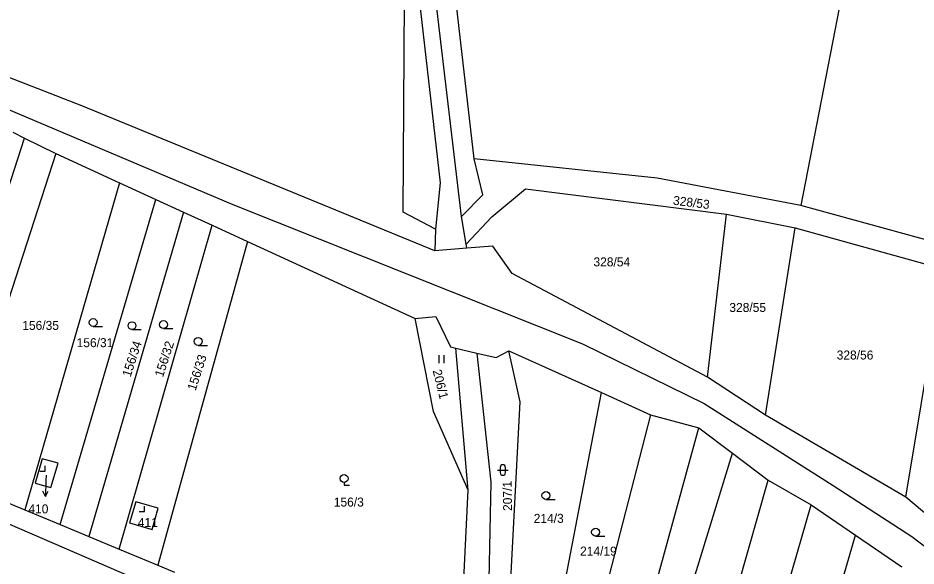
# Model space of a CAD drawing. Extents: x -783948 to -781889, y -1005870 to -1004430.
# Drawn here: x -782682.3 to -782512.1, y -1005229.8 to -1005126 of the extents above; entities that cross this region are included whole.
import ezdxf

# ---------------------------------------------------------------- set-up
doc = ezdxf.new("R2010")
doc.units = 0
for name, color, linetype in [('Vrstva 1', 7, 'Continuous'), ('Vrstva 2', 7, 'Continuous'), ('Vrstva 3', 7, 'Continuous'), ('Vrstva 6', 7, 'Continuous'), ('Vrstva 7', 7, 'Continuous')]:
    doc.layers.add(name, color=color, linetype=linetype)

msp = doc.modelspace()

# ---------------------------------------------------------------- linework, layer by layer
at = {"layer": 'Vrstva 1'}
for p, q in [((-782683.3, -1005147.64), (-782681.06, -1005148.77)), ((-782700.91, -1005209.8), (-782681.06, -1005148.77)), ((-782681.06, -1005148.77), (-782675.11, -1005151.66)), ((-782675.11, -1005151.66), (-782694.84, -1005212.38)), ((-782675.11, -1005151.66), (-782663.04, -1005157.2)), ((-782663.04, -1005157.2), (-782681.01, -1005219.18)), ((-782663.04, -1005157.2), (-782656.17, -1005160.35)), ((-782674.31, -1005221.97), (-782656.17, -1005160.35)), ((-782656.17, -1005160.35), (-782650.91, -1005162.76)), ((-782506.17, -1005169.11), (-782533.94, -1005161.48)), ((-782650.91, -1005162.76), (-782668.89, -1005224.22)), ((-782650.91, -1005162.76), (-782645.48, -1005165.25)), ((-782551.65, -1005194.04), (-782548.07, -1005163.13)), ((-782548.07, -1005163.13), (-782535.05, -1005165.75)), ((-782597.38, -1005168.84), (-782598.25, -1005163.56)), ((-782663.16, -1005226.6), (-782645.48, -1005165.25)), ((-782645.48, -1005165.25), (-782638.79, -1005168.32)), ((-782603.17, -1005166.01), (-782603.34, -1005170.09)), ((-782540.66, -1005201.24), (-782535.05, -1005165.75)), ((-782535.05, -1005165.75), (-782506.92, -1005173.54)), ((-782638.79, -1005168.32), (-782655.82, -1005229.65)), ((-782638.79, -1005168.32), (-782607.01, -1005182.91)), ((-782597.26, -1005169.59), (-782603.34, -1005170.09)), ((-782597.26, -1005169.59), (-782597.38, -1005168.84)), ((-782514.05, -1005216.76), (-782506.92, -1005173.54)), ((-782599.33, -1005188.51), (-782595.36, -1005189.48)), ((-782596.97, -1005215.45), (-782599.33, -1005188.51)), ((-782589.32, -1005189.04), (-782571.74, -1005196.93)), ((-782540.66, -1005201.24), (-782551.65, -1005194.04)), ((-782586.82, -1005275.72), (-782571.74, -1005196.93)), ((-782571.74, -1005196.93), (-782562.45, -1005201.15)), ((-782562.45, -1005201.15), (-782581.31, -1005274.34)), ((-782562.45, -1005201.15), (-782553.29, -1005203.6)), ((-782514.05, -1005216.76), (-782540.66, -1005201.24)), ((-782573.67, -1005278.05), (-782553.29, -1005203.6)), ((-782553.29, -1005203.6), (-782546.93, -1005208.45)), ((-782569, -1005280.32), (-782546.93, -1005208.45)), ((-782546.93, -1005208.45), (-782540.15, -1005213.57)), ((-782695.19, -1005213.28), (-782681.01, -1005219.18)), ((-782560.39, -1005284.52), (-782540.15, -1005213.57)), ((-782540.15, -1005213.57), (-782531.97, -1005218.22)), ((-782652.68, -1005235.38), (-782700.06, -1005214.94)), ((-782681.01, -1005219.18), (-782674.31, -1005221.97)), ((-782551.57, -1005285.44), (-782531.97, -1005218.22)), ((-782531.97, -1005218.22), (-782523.58, -1005223.98)), ((-782674.31, -1005221.97), (-782668.89, -1005224.22)), ((-782668.89, -1005224.22), (-782663.16, -1005226.6)), ((-782541.74, -1005286.41), (-782523.58, -1005223.98)), ((-782523.58, -1005223.98), (-782514.79, -1005229.97)), ((-782663.16, -1005226.6), (-782655.82, -1005229.65)), ((-782655.82, -1005229.65), (-782652.65, -1005230.97))]:
    msp.add_line(p, q, dxfattribs=at)
for points in [[(-782603.17, -1005166.01), (-782609.32, -1005162.79), (-782608.8, -1005082.15), (-782604.16, -1005035.19), (-782599.71, -1005013.15), (-782586.95, -1004973.45)], [(-782586.95, -1004973.45), (-782597.75, -1005020.65), (-782600.85, -1005037.62), (-782602.65, -1005059.62), (-782606.52, -1005120.13), (-782602.3, -1005157.2), (-782603.17, -1005166.01)], [(-782598.25, -1005163.56), (-782603.01, -1005123.54), (-782599.4, -1005065.13), (-782594.84, -1005033.29), (-782586.07, -1004994.91)], [(-782595.88, -1005152.67), (-782599.4, -1005121.85), (-782597.87, -1005069.24), (-782592.64, -1005033.25), (-782584.34, -1004995.55)], [(-782483.01, -1005052.11), (-782511.95, -1005043.46), (-782520.61, -1005092.84), (-782533.94, -1005161.48)], [(-782603.34, -1005170.09), (-782670.21, -1005142.63), (-782705.63, -1005128.88), (-782803.2, -1005086.94), (-782810.41, -1005084.95), (-782850.5, -1005065.89)], [(-782598.25, -1005163.56), (-782594.21, -1005159.46), (-782595.88, -1005152.67)], [(-782533.94, -1005161.48), (-782561.15, -1005156.31), (-782595.88, -1005152.67)], [(-782597.38, -1005168.84), (-782592.52, -1005163.67), (-782586.11, -1005158.34), (-782548.07, -1005163.13)], [(-782551.65, -1005194.04), (-782588.65, -1005174.4), (-782592.33, -1005169.18), (-782597.26, -1005169.59)], [(-782607.01, -1005182.91), (-782603.11, -1005182.52), (-782600.34, -1005188.27), (-782599.33, -1005188.51)], [(-782596.97, -1005215.45), (-782603.56, -1005200.53), (-782607.01, -1005182.91)], [(-782595.36, -1005189.48), (-782591.71, -1005190.27), (-782589.32, -1005189.04)], [(-782595.36, -1005189.48), (-782592.73, -1005213.92), (-782593.1, -1005232.35), (-782594, -1005268.18)], [(-782590.78, -1005268.46), (-782587.12, -1005198.7), (-782589.32, -1005189.04)], [(-782674.71, -1005210.35), (-782677.69, -1005209.49), (-782679.03, -1005214.11), (-782676.06, -1005214.96), (-782674.71, -1005210.35)], [(-782601.33, -1005274.67), (-782599.52, -1005267.38), (-782596.97, -1005215.45)], [(-782660, -1005217.63), (-782661.16, -1005221.64), (-782656.9, -1005222.87), (-782655.74, -1005218.86), (-782660, -1005217.63)], [(-782402.29, -1005331.02), (-782436.69, -1005287.11), (-782455.38, -1005266.01), (-782514.05, -1005216.76)]]:
    msp.add_lwpolyline(points, dxfattribs=at)
at = {"layer": 'Vrstva 3'}
for p, q in [((-782668.06, -1005184.42), (-782666.31, -1005184.42)), ((-782660.7, -1005185.02), (-782658.95, -1005185.02)), ((-782654.73, -1005184.82), (-782652.98, -1005184.82)), ((-782648.16, -1005188), (-782646.41, -1005188)), ((-782602.52, -1005191.39), (-782602.52, -1005189.89)), ((-782601.52, -1005191.39), (-782601.52, -1005189.89)), ((-782677.17, -1005211.83), (-782677.17, -1005210.83)), ((-782678.17, -1005211.83), (-782677.17, -1005211.83)), ((-782591.43, -1005211.62), (-782589.43, -1005211.62)), ((-782590.93, -1005211.12), (-782590.93, -1005212.12)), ((-782589.93, -1005212.12), (-782589.93, -1005211.12)), ((-782620.51, -1005213.98), (-782620.51, -1005214.48)), ((-782620.51, -1005214.48), (-782619.51, -1005214.48)), ((-782582.26, -1005217.19), (-782580.51, -1005217.19)), ((-782658.36, -1005219.49), (-782658.36, -1005218.49)), ((-782659.36, -1005219.49), (-782658.36, -1005219.49)), ((-782572.85, -1005224.14), (-782571.1, -1005224.14))]:
    msp.add_line(p, q, dxfattribs=at)
for centre in [(-782668.06, -1005183.67), (-782660.7, -1005184.27), (-782654.73, -1005184.07), (-782648.16, -1005187.25), (-782620.51, -1005213.23), (-782582.26, -1005216.44), (-782572.85, -1005223.39)]:
    msp.add_circle(centre, 0.75, dxfattribs=at)
for centre, start, end in [((-782590.43, -1005211.12), 0, 180), ((-782590.43, -1005212.12), 180, 359.9879)]:
    msp.add_arc(centre, 0.5, start, end, dxfattribs=at)
at = {"layer": 'Vrstva 6'}
for p, q in [((-782841.72, -1005076.44), (-782641.6, -1005161.34)), ((-782641.6, -1005161.34), (-782575.36, -1005187.7)), ((-782575.36, -1005187.7), (-782552.26, -1005199.03)), ((-782552.26, -1005199.03), (-782527.86, -1005214.56)), ((-782527.86, -1005214.56), (-782512.93, -1005224.22)), ((-782512.93, -1005224.22), (-782493.17, -1005239.34))]:
    msp.add_line(p, q, dxfattribs=at)
at = {"layer": 'Vrstva 7'}
for p, q in [((-782677.01, -1005213.63), (-782677.11, -1005216.63)), ((-782676.97, -1005212.6), (-782677.01, -1005213.63)), ((-782677.11, -1005216.63), (-782677.58, -1005215.61)), ((-782677.11, -1005216.63), (-782676.58, -1005215.65))]:
    msp.add_line(p, q, dxfattribs=at)

# ---------------------------------------------------------------- texts
at = {"layer": 'Vrstva 2'}
for s, rotation, p in [('328/53', 353, (-782558.25, -1005161.34)), ('156/34', 72, (-782660.98, -1005194.12)), ('156/32', 72, (-782654.84, -1005194.15)), ('156/33', 72, (-782648.65, -1005196.71)), ('206/1', 284, (-782603.74, -1005192.8)), ('207/1', 91, (-782588.66, -1005219.36))]:
    msp.add_text(s, height=1.7, rotation=rotation, dxfattribs=at).set_placement(p)
for s, p in [('328/54', (-782573.25, -1005173.04)), ('328/55', (-782547.5, -1005181.67)), ('156/35', (-782681.49, -1005185.07)), ('156/31', (-782671.19, -1005188.34)), ('328/56', (-782527.16, -1005190.68)), ('156/3', (-782622.46, -1005218.54)), ('410', (-782680.33, -1005219.83)), ('411', (-782659.6, -1005222.41)), ('214/3', (-782584.58, -1005221.63)), ('214/19', (-782575.79, -1005227.83))]:
    msp.add_text(s, height=1.7, dxfattribs=at).set_placement(p)

doc.saveas('drawing.dxf')
